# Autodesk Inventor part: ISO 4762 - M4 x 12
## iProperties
Library Location: C:\Program Files\Autodesk\Inventor 6\content
Library: local
SubLibrary: ISO
Family: 13
Member: 400
Member Major Revision: 1
Member Minor Revision: 1
Comments: To add or edit properties for Autodesk Inventor files, use iProperties.
Created: 2003-05
Part Number: ISO 4762 - M4 x 12
Vendor: Autodesk Inc.
Document SubType Name: Modeling
Designer: Philippe
Description: Vis cylindrique à six pans creux
Standard: ISO 4762 M4 x 12
Alert: To add or edit properties for Autodesk Inventor files, use iProperties.
Control State: 0
Master: False
Checked Out: False
Shininess: 64.0
Length Units: 11269
Angle Units: 11279
Time Units: 11290
Mass Units: 11283
Length Display Precision: 3
Angle Display Precision: 2
Compacted: True
EGR: 1
Density: 0.0
Volumn: 0.0
Area: 0.0
PropertySet Name: Model Information
Author: Philippe
Revision Number: 1
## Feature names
1. Corps [Revolution]
2. Fente [Extrusion]
3. Congé1 [Fillet]
4. Chanfrein1 [Chamfer]
